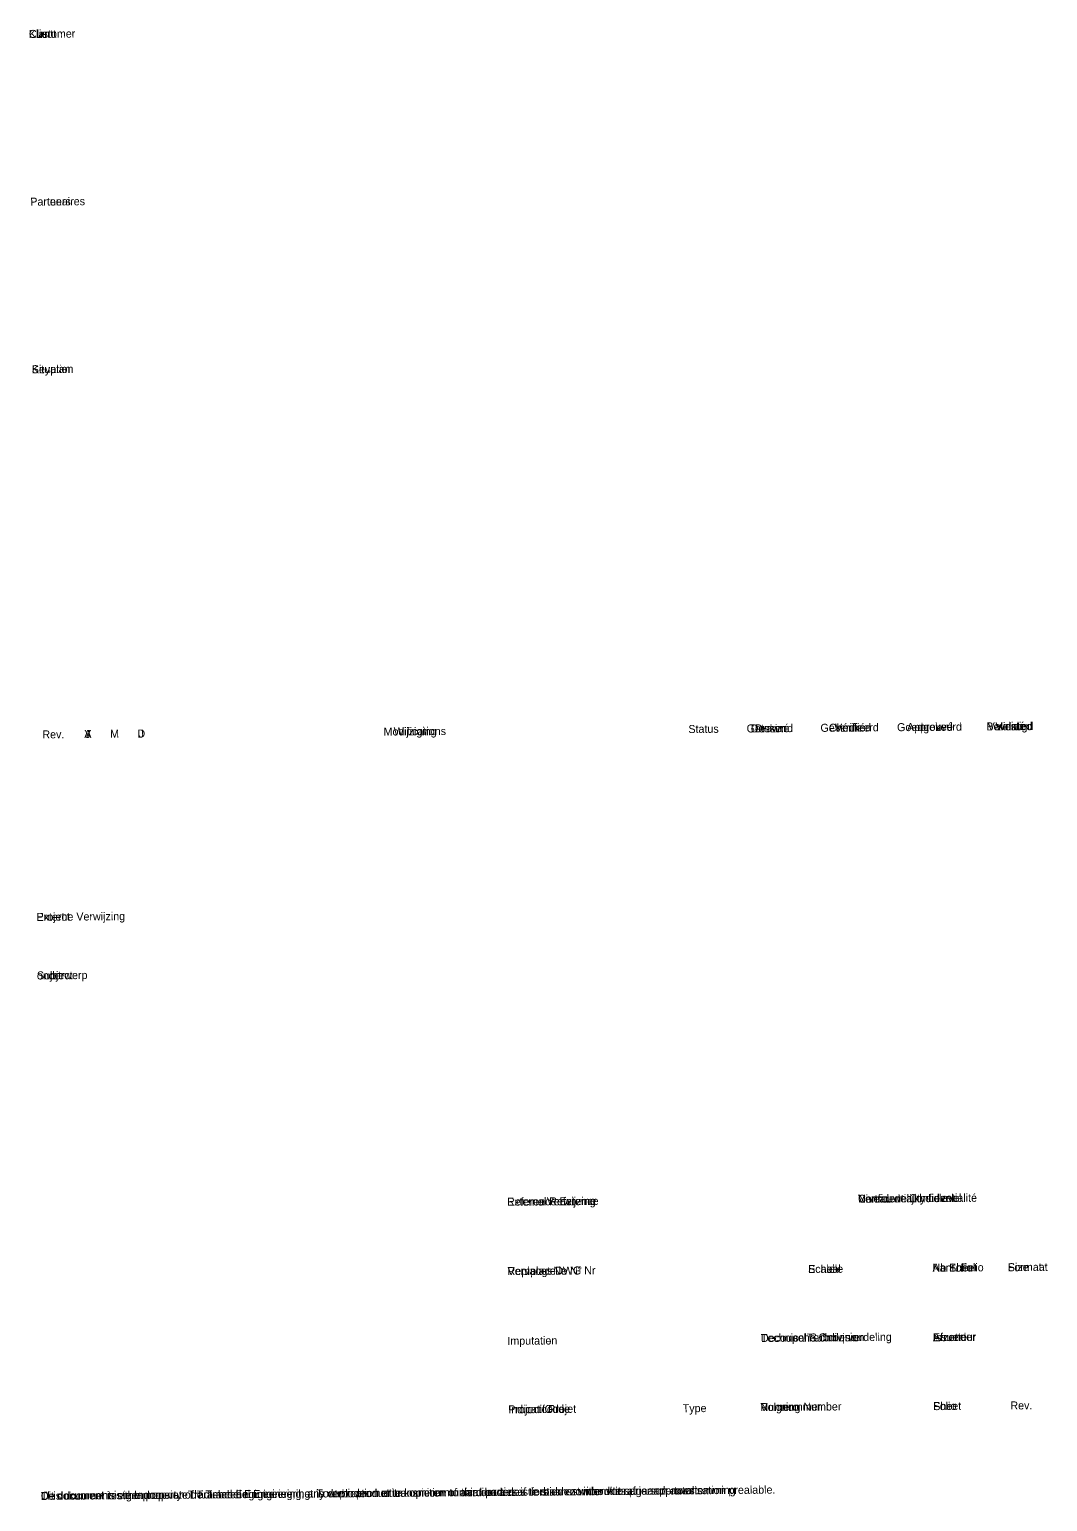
# Model space of a CAD drawing. Extents: x -932734 to -932083, y -737151 to -736752.
# Drawn here: x -932178.6 to -932083.2, y -737151.2 to -737013.3 of the extents above; entities that cross this region are included whole.
import ezdxf

# ---------------------------------------------------------------- set-up
doc = ezdxf.new("R2010")
doc.units = 0
for name, color, linetype in [('02 BORDER TEXT', 7, 'Continuous'), ('BorderColor', 7, 'Continuous'), ('WA_81_PODBARVENÍ SO', 7, 'Continuous')]:
    doc.layers.add(name, color=color, linetype=linetype)

msp = doc.modelspace()

# ---------------------------------------------------------------- texts
at = {"layer": '02 BORDER TEXT'}
for s, p in [('Client', (-932178.66, -737014.06)), ('Partenaires', (-932178.53, -737029.78)), ('Situation', (-932178.39, -737045.49)), ('Vérifié', (-932103.1, -737079.09)), ('Approuvé', (-932096.36, -737079.03)), ('Validé', (-932088.07, -737078.96)), ('Rev.', (-932177.4, -737079.72)), ('A', (-932173.47, -737079.68)), ('M', (-932171.05, -737079.66)), ('J', (-932168.38, -737079.64)), ('Modifications', (-932145.42, -737079.45)), ('Status', (-932116.85, -737079.21)), ('Dessiné', (-932111.01, -737079.16)), ('Projet', (-932177.95, -737096.82)), ('Sujet', (-932177.91, -737102.31)), ('Niveau de Confidentialité', (-932100.95, -737123.24)), ('Reference Externe', (-932133.85, -737123.52)), ('Remplace le N°', (-932133.8, -737130.02)), ('Echelle', (-932105.63, -737129.83)), ('Nb Folio', (-932093.97, -737129.71)), ('Format', (-932086.91, -737129.66)), ('Imputation', (-932133.82, -737136.56)), ('Decoupe Technique', (-932110.05, -737136.29)), ('Emetteur', (-932093.93, -737136.22)), ('Indicatif Projet', (-932133.73, -737142.98)), ('Type', (-932117.38, -737142.88)), ('Numero', (-932110.09, -737142.77)), ('Folio', (-932093.9, -737142.68)), ('Rev.', (-932086.67, -737142.62)), ('Ce document reste la propriete de Tractebel Engineering. Toute reproduction ou communication a des tiers en est interdite sans son autorisation prealable.', (-932177.54, -737151.09))]:
    msp.add_text(s, height=0.75, rotation=0.4883, dxfattribs=at).set_placement(p)
at = {"layer": 'BorderColor'}
for s, p in [('Customer', (-932178.66, -737014.06)), ('Partners', (-932178.53, -737029.78)), ('Keyplan', (-932178.39, -737045.49)), ('Approved', (-932096.36, -737079.03)), ('Validated', (-932088.8, -737078.97)), ('Rev.', (-932177.4, -737079.72)), ('Y', (-932173.47, -737079.68)), ('M', (-932171.05, -737079.66)), ('D', (-932168.49, -737079.64)), ('Modifications', (-932145.42, -737079.45)), ('Status', (-932116.85, -737079.21)), ('Drawn', (-932110.63, -737079.15)), ('Checked', (-932103.68, -737079.09)), ('Project', (-932177.95, -737096.82)), ('Subject', (-932177.91, -737102.31)), ('Confidentiality Level', (-932100.95, -737123.24)), ('External Reference', (-932133.85, -737123.52)), ('Replaces DWG Nr', (-932133.8, -737130.02)), ('Scale', (-932105.63, -737129.83)), ('Nb Sheet', (-932093.97, -737129.71)), ('Size', (-932086.91, -737129.66)), ('Imputation', (-932133.82, -737136.56)), ('Technical Subdivision', (-932110.05, -737136.29)), ('Issuer', (-932093.93, -737136.22)), ('Project Code', (-932133.73, -737142.98)), ('Type', (-932117.38, -737142.88)), ('Running Number', (-932110.09, -737142.77)), ('Sheet', (-932093.9, -737142.68)), ('Rev.', (-932086.67, -737142.62)), ('This document is the property of Tractebel Engineering, any duplication or transmition to third parties is forbidden without its prior approval.', (-932177.54, -737151.09))]:
    msp.add_text(s, height=0.75, rotation=0.4883, dxfattribs=at).set_placement(p)
at = {"layer": 'WA_81_PODBARVENÍ SO'}
for s, p in [('Klant', (-932178.66, -737014.06)), ('Partners', (-932178.53, -737029.78)), ('Situatie', (-932178.39, -737045.49)), ('Goedgekeurd', (-932097.29, -737079.04)), ('Bevestigd', (-932088.92, -737078.97)), ('Rev.', (-932177.4, -737079.72)), ('J', (-932173.38, -737079.68)), ('M', (-932171.05, -737079.66)), ('D', (-932168.49, -737079.64)), ('Wijziging', (-932144.46, -737079.44)), ('Status', (-932116.85, -737079.21)), ('Getekend', (-932111.39, -737079.16)), ('Geverifieerd', (-932104.47, -737079.1)), ('Externe Verwijzing', (-932177.95, -737096.82)), ('onderwerp', (-932177.91, -737102.31)), ('Vertrouwelijkheidlevel', (-932100.95, -737123.24)), ('Externe Verwijzing', (-932133.85, -737123.52)), ('Vervangt Nr', (-932133.8, -737130.02)), ('Schaal', (-932105.63, -737129.83)), ('Aant. Folio', (-932093.97, -737129.71)), ('Formaat', (-932086.91, -737129.66)), ('Imputatie', (-932133.82, -737136.56)), ('Technische Onderverdeling', (-932110.05, -737136.29)), ('Afzender', (-932093.93, -737136.22)), ('Projectcode', (-932133.73, -737142.98)), ('Type', (-932117.38, -737142.88)), ('Volgnummer', (-932110.09, -737142.77)), ('Folio', (-932093.9, -737142.68)), ('Rev.', (-932086.67, -737142.62)), ('Dit dokument is eigendom van Tractebel Engineering; het is verboden het te kopieren of aan derden af te staan zonder voorafgaande toestemming', (-932177.54, -737151.09))]:
    msp.add_text(s, height=0.75, rotation=0.4883, dxfattribs=at).set_placement(p)

doc.saveas('drawing.dxf')
